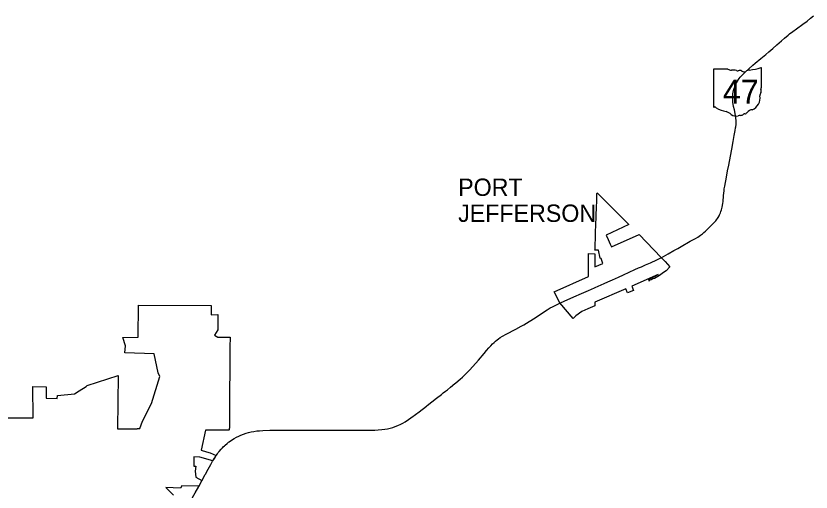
# Model space of a CAD drawing. Extents: x 0 to 34, y 0 to 22.
# Drawn here: x 5.5324 to 5.9007, y 18.3979 to 18.6182 of the extents above; entities that cross this region are included whole.
import ezdxf

# ---------------------------------------------------------------- set-up
doc = ezdxf.new("R2010")
doc.units = 0
for name, color, linetype in [('GM_X_Corporation', 7, 'Continuous'), ('GM_X_Corporation_Text', 7, 'Continuous'), ('GM_X_State_Location', 7, 'Continuous'), ('GM_X_State_Route', 7, 'Continuous'), ('GM_X_State_Shield', 7, 'Continuous')]:
    doc.layers.add(name, color=color, linetype=linetype)

msp = doc.modelspace()

# ---------------------------------------------------------------- linework, layer by layer
at = {"layer": 'GM_X_Corporation'}
msp.add_lwpolyline([(5.808174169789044, 18.511366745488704), (5.821044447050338, 18.517024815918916), (5.831236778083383, 18.506413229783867), (5.833056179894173, 18.50454531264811), (5.83531645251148, 18.50216216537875), (5.833549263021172, 18.500257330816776), (5.832319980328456, 18.49943728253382), (5.8310200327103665, 18.49852072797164), (5.830432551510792, 18.498096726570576), (5.829741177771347, 18.49766429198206), (5.828184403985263, 18.49679150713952), (5.82736013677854, 18.49652097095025), (5.8266708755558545, 18.49617554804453), (5.8258619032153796, 18.4959203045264), (5.825667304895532, 18.495515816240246), (5.825606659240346, 18.496414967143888), (5.828199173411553, 18.497675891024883), (5.829847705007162, 18.498591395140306), (5.817588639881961, 18.49312686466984), (5.8184746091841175, 18.491164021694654), (5.815717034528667, 18.490082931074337), (5.814906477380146, 18.491911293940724), (5.800549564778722, 18.485816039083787), (5.800520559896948, 18.484137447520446), (5.797253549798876, 18.482696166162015), (5.7945560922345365, 18.48140518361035), (5.791649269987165, 18.47942493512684), (5.790495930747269, 18.478195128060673), (5.784341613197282, 18.485399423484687), (5.781615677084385, 18.490484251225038), (5.797594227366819, 18.497718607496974), (5.79758579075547, 18.50824897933), (5.800564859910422, 18.508157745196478), (5.800546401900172, 18.50210468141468), (5.804286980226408, 18.503680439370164), (5.8034843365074, 18.505935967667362), (5.803039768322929, 18.506124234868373), (5.80217014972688, 18.50983264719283), (5.800589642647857, 18.50988538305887), (5.800654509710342, 18.51032625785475), (5.800682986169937, 18.512432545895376), (5.800763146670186, 18.51516744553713), (5.800831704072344, 18.51695467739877), (5.800899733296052, 18.518895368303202), (5.800971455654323, 18.52077910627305), (5.800999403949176, 18.521724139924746), (5.801027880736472, 18.522620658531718), (5.801081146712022, 18.524255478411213), (5.801144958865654, 18.52591930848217), (5.801186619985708, 18.526787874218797), (5.801269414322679, 18.52873595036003), (5.8013337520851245, 18.530422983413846), (5.801385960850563, 18.53184633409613), (5.801461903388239, 18.534006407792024), (5.801517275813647, 18.53595606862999), (5.801530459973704, 18.536375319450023), (5.816220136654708, 18.521714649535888), (5.805843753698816, 18.516747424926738), (5.8067154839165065, 18.5147023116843), (5.807585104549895, 18.512668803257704)], close=True, dxfattribs=at)
msp.add_lwpolyline([(5.525409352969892, 18.432222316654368), (5.540361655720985, 18.432277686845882), (5.540285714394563, 18.44669050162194), (5.546459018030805, 18.446609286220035), (5.546450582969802, 18.44519226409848), (5.546456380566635, 18.44131404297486), (5.551506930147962, 18.441193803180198), (5.551607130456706, 18.44264088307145), (5.559566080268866, 18.44336337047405), (5.561653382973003, 18.444678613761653), (5.56485710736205, 18.44669788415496), (5.565389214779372, 18.447169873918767), (5.579684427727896, 18.451787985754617), (5.579492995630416, 18.427136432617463), (5.588597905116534, 18.427111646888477), (5.588613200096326, 18.42738851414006), (5.589835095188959, 18.42738851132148), (5.591016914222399, 18.4306360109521), (5.595184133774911, 18.438813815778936), (5.599109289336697, 18.451374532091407), (5.598347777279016, 18.453032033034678), (5.596425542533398, 18.46189910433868), (5.582826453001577, 18.462407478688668), (5.5830679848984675, 18.465571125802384), (5.5818787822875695, 18.469464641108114), (5.58906145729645, 18.469504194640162), (5.589233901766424, 18.48436051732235), (5.622789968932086, 18.48419123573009), (5.622814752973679, 18.47998868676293), (5.625856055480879, 18.480037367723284), (5.6258510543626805, 18.472996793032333), (5.6244075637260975, 18.470464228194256), (5.625848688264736, 18.469606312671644), (5.627700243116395, 18.469601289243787), (5.6315752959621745, 18.469513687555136), (5.631513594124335, 18.46488450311), (5.631496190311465, 18.461457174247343), (5.631439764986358, 18.45771553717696), (5.631392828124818, 18.453867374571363), (5.631412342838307, 18.451968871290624), (5.631344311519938, 18.446645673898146), (5.6313116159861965, 18.436314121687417), (5.631312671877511, 18.434841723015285), (5.6313158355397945, 18.430883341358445), (5.631291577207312, 18.42824547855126), (5.631277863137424, 18.427930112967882), (5.631262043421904, 18.42755885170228), (5.631230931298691, 18.427226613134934), (5.631191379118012, 18.426949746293), (5.631143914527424, 18.426744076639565), (5.6310732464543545, 18.426483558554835), (5.620133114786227, 18.426476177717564), (5.618261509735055, 18.417322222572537), (5.62066944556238, 18.41645259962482), (5.622309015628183, 18.41612563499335), (5.625061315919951, 18.414806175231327), (5.62495900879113, 18.414663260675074), (5.624308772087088, 18.41365336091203), (5.62390955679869, 18.413002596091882), (5.623537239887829, 18.412355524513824), (5.617598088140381, 18.414120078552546), (5.6147413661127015, 18.41416859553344), (5.614822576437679, 18.409916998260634), (5.615779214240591, 18.409900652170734), (5.615344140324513, 18.407640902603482), (5.615712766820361, 18.404750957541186), (5.618474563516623, 18.40320367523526), (5.618475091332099, 18.403199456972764), (5.617073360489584, 18.400593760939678), (5.609287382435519, 18.400845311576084), (5.608588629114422, 18.399754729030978), (5.601788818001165, 18.400024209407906), (5.605381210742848, 18.396482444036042)], dxfattribs=at)
at = {"layer": 'GM_X_State_Route'}
for p, q in [((5.8307983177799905, 18.506133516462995), (5.831256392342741, 18.506367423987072)), ((5.618494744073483, 18.403153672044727), (5.620112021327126, 18.406043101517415)), ((5.617093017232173, 18.40054797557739), (5.618494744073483, 18.403153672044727))]:
    msp.add_line(p, q, dxfattribs=at)
for points in [[(5.860446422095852, 18.538075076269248), (5.860468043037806, 18.538236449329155), (5.860677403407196, 18.539487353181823), (5.861447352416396, 18.543582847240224), (5.862027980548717, 18.54658512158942), (5.8625252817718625, 18.549227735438), (5.863307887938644, 18.553317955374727), (5.863913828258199, 18.55652959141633), (5.86456512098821, 18.560056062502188), (5.865119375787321, 18.562903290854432), (5.865538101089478, 18.565184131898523), (5.865745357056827, 18.566431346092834), (5.865824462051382, 18.56692970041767), (5.865879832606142, 18.567348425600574), (5.865921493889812, 18.56772548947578), (5.865942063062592, 18.568129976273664), (5.865962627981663, 18.568590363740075), (5.865962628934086, 18.568995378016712), (5.865955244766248, 18.56955332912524), (5.865934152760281, 18.57004852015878), (5.865884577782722, 18.570836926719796), (5.86584239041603, 18.57126936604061), (5.865786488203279, 18.571729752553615), (5.8657094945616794, 18.572127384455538), (5.865144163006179, 18.574758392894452), (5.864795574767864, 18.576357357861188), (5.864591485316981, 18.577448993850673), (5.864480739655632, 18.578235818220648), (5.864404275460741, 18.579080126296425), (5.864370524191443, 18.57987433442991), (5.864381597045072, 18.580828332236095), (5.86442220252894, 18.581516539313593), (5.8645023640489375, 18.582201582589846), (5.864629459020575, 18.582933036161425), (5.864803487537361, 18.583709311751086), (5.865076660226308, 18.58467754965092), (5.865344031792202, 18.58548230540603), (5.8656166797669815, 18.586173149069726), (5.865903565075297, 18.586800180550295), (5.866173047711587, 18.587318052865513), (5.866594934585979, 18.58805266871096), (5.867051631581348, 18.588767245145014), (5.867419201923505, 18.58928669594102), (5.867908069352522, 18.589913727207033), (5.8684285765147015, 18.590514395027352), (5.869160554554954, 18.59127854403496), (5.8701483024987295, 18.592233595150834), (5.871812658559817, 18.593776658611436), (5.873702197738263, 18.595464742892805), (5.874786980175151, 18.596389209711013), (5.877362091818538, 18.598491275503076), (5.879693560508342, 18.60038819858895), (5.881152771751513, 18.601600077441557), (5.88302279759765, 18.603223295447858), (5.8848738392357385, 18.604868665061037), (5.886993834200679, 18.60676980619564), (5.888392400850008, 18.60797588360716), (5.8899929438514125, 18.609298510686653), (5.890723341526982, 18.609879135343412), (5.892187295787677, 18.611005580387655), (5.893967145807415, 18.612326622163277), (5.89683335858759, 18.614393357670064), (5.89883153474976, 18.615857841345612), (5.900454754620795, 18.617117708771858), (5.901859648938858, 18.618231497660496)], [(5.83896372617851, 18.510651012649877), (5.840524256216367, 18.511541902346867), (5.844750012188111, 18.5139266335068), (5.847136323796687, 18.515275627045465), (5.848217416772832, 18.515929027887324), (5.849437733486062, 18.516750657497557), (5.85036009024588, 18.5174488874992), (5.8510535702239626, 18.518013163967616), (5.851757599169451, 18.51864388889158), (5.852933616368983, 18.519776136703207), (5.854088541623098, 18.520934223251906), (5.854994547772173, 18.521819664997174), (5.85605718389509, 18.52291657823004), (5.856518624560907, 18.52341651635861), (5.856877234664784, 18.5238647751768), (5.85726589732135, 18.524423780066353), (5.857597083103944, 18.52495905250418), (5.858058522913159, 18.525783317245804), (5.858294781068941, 18.52625214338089), (5.858659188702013, 18.527066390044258), (5.858948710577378, 18.527798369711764), (5.859168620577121, 18.528443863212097), (5.859342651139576, 18.52904769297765), (5.859489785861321, 18.52965943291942), (5.859647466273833, 18.53048527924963), (5.859814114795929, 18.53152207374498), (5.859894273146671, 18.532252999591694), (5.860142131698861, 18.53519357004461), (5.860349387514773, 18.53734626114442), (5.860446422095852, 18.538075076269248)], [(5.831256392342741, 18.506367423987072), (5.834415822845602, 18.508095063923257), (5.837180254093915, 18.50963285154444), (5.83896372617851, 18.510651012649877)], [(5.784361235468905, 18.485353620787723), (5.786665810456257, 18.486380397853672), (5.789119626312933, 18.48747836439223), (5.790854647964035, 18.488242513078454), (5.794274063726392, 18.489750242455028), (5.795357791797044, 18.490221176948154), (5.7976549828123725, 18.491232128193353), (5.80030761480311, 18.492404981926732), (5.800732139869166, 18.492595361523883), (5.8035155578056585, 18.49384257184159), (5.80488564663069, 18.49444270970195), (5.806567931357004, 18.495200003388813), (5.8086694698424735, 18.496136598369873), (5.811480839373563, 18.497380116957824), (5.813803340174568, 18.49841849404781), (5.81637845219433, 18.4995829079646), (5.8190558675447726, 18.500823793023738), (5.820820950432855, 18.50161114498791), (5.822154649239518, 18.50219282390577), (5.823984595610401, 18.50302711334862), (5.82404946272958, 18.503058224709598), (5.826251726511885, 18.504004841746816), (5.829271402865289, 18.505353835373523), (5.8307983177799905, 18.506133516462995)], [(5.735987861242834, 18.44830445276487), (5.737227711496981, 18.449332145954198), (5.738181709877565, 18.450161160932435), (5.739233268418, 18.45111832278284), (5.7403011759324, 18.452135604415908), (5.741273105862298, 18.453101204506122), (5.742489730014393, 18.454343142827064), (5.7440596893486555, 18.456049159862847), (5.746595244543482, 18.458944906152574), (5.749207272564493, 18.461983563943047), (5.750353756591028, 18.46336209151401), (5.75144908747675, 18.46464885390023), (5.752331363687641, 18.465631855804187), (5.753100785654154, 18.466432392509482), (5.753862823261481, 18.46716700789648), (5.754536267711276, 18.467763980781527), (5.755317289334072, 18.468397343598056), (5.755952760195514, 18.46887249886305), (5.756736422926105, 18.469413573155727), (5.757760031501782, 18.470072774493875), (5.759386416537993, 18.47095135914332), (5.763962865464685, 18.473354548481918), (5.766383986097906, 18.474640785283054), (5.7675826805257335, 18.475304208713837), (5.768914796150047, 18.476054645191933), (5.7721496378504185, 18.47803225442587), (5.773823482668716, 18.479133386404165), (5.776807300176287, 18.481121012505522), (5.778391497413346, 18.482168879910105), (5.779864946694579, 18.483098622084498), (5.78087748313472, 18.483671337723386), (5.782768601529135, 18.484617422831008), (5.784361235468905, 18.485353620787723)], [(5.6309035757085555, 18.420920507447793), (5.6312004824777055, 18.421150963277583), (5.632284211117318, 18.421907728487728), (5.63348606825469, 18.422678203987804), (5.63454026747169, 18.42328678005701), (5.63557600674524, 18.42381941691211), (5.636542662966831, 18.42425132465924), (5.637726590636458, 18.424710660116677), (5.639029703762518, 18.42514942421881), (5.640147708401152, 18.425473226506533), (5.6413817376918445, 18.425770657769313), (5.642577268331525, 18.42599794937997), (5.6439389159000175, 18.4261888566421), (5.645148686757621, 18.42630592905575), (5.646783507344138, 18.426396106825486), (5.649947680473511, 18.426471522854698), (5.653586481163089, 18.42650368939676), (5.657223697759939, 18.426516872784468), (5.659386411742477, 18.426532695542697), (5.663076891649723, 18.42651950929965), (5.666979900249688, 18.42654271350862), (5.669394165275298, 18.426549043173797), (5.670670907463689, 18.42654218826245), (5.675892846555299, 18.42651476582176), (5.680059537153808, 18.426527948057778), (5.681747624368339, 18.426539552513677), (5.685967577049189, 18.42654060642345), (5.693300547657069, 18.426527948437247), (5.694828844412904, 18.42653269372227), (5.697654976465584, 18.42658543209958), (5.698572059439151, 18.426602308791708), (5.700203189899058, 18.426674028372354), (5.7018817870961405, 18.42681430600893), (5.703184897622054, 18.426985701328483), (5.704426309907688, 18.427214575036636), (5.705758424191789, 18.427524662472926), (5.706922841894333, 18.427850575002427), (5.708066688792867, 18.428241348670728), (5.709239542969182, 18.42870753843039), (5.710615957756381, 18.429329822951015), (5.711566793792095, 18.429812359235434), (5.712705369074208, 18.430469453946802), (5.714263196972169, 18.43145403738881), (5.716424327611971, 18.433019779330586), (5.7168762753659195, 18.433352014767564), (5.717469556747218, 18.433787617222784), (5.719184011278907, 18.435103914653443), (5.722503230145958, 18.437704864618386), (5.7228581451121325, 18.43799122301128), (5.727244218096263, 18.441397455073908), (5.7294470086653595, 18.443114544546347), (5.730276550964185, 18.443765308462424), (5.731318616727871, 18.4445727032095), (5.732238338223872, 18.445278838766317), (5.733642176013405, 18.446390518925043), (5.735726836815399, 18.448088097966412), (5.735987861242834, 18.44830445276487)], [(5.625080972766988, 18.41476038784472), (5.625690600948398, 18.41561207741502), (5.626121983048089, 18.41615631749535), (5.626496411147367, 18.416604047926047), (5.627494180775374, 18.41776529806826), (5.62800361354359, 18.41831058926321), (5.6284508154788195, 18.41879629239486), (5.628935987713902, 18.419281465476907), (5.629315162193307, 18.419612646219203), (5.630280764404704, 18.420437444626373), (5.6309035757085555, 18.420920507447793)], [(5.620112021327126, 18.406043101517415), (5.620194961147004, 18.406191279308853), (5.621465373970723, 18.40849057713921), (5.6226218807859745, 18.410630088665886), (5.623466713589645, 18.41215310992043), (5.623556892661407, 18.41230973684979)], [(5.623556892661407, 18.41230973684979), (5.623929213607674, 18.412956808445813), (5.6243284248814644, 18.41360757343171), (5.624978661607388, 18.414617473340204), (5.625080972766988, 18.41476038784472)], [(5.614172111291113, 18.39524730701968), (5.6142120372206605, 18.39532076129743), (5.615428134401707, 18.39753990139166), (5.617093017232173, 18.40054797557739)]]:
    msp.add_lwpolyline(points, dxfattribs=at)
at = {"layer": 'GM_X_State_Shield'}
for p, q in [((5.855407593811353, 18.593346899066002), (5.855407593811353, 18.576362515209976)), ((5.862181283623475, 18.593639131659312), (5.855627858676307, 18.593639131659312)), ((5.877785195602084, 18.585175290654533), (5.877785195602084, 18.594060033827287)), ((5.877783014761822, 18.585177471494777), (5.877785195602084, 18.585175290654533))]:
    msp.add_line(p, q, dxfattribs=at)
for centre, radius, start, end in [((5.855663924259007, 18.59338306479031), 0.0002592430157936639, 98.1301027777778, 188.13010277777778), ((5.863741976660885, 18.59561084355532), 0.0025145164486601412, 231.61950555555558, 271.11188333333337), ((5.864575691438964, 18.584103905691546), 0.009027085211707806, 80.48669166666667, 94.98826944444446), ((5.866625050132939, 18.593471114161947), 0.0007254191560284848, 219.79206111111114, 297.1023694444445), ((5.867689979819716, 18.59150804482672), 0.0015082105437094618, 54.466683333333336, 119.14113055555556), ((5.869636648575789, 18.594200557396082), 0.0018143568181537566, 233.85620555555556, 294.82819166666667), ((5.872840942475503, 18.58845158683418), 0.004774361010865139, 97.34618055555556, 120.7688527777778), ((5.869813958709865, 18.616794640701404), 0.02373123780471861, 275.8444694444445, 288.9064527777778), ((5.877536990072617, 18.594096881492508), 0.000249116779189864, 351.8620861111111, 97.738), ((5.877727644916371, 18.584523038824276), 0.00038552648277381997, 107.94398333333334, 210.33696666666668), ((5.877519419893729, 18.585140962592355), 0.0002666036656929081, 289.6038111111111, 7.734130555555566), ((5.871143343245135, 18.580326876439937), 0.005935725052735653, 292.3088861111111, 8.985838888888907), ((5.878677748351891, 18.581457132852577), 0.001683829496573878, 136.80649722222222, 186.92959444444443), ((5.875274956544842, 18.583399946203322), 0.002314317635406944, 340.0329638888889, 23.649566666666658), ((5.855666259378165, 18.576325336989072), 0.00026154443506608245, 171.9583861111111, 258.30661388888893), ((5.855705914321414, 18.578062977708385), 0.0019959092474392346, 267.33899444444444, 280.6038555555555), ((5.856114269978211, 18.575382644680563), 0.000719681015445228, 29.748380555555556, 93.27174722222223), ((5.865200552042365, 18.590642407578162), 0.017137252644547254, 240.41292222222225, 257.1985), ((5.860091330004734, 18.568732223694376), 0.0053619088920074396, 47.184155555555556, 75.83597222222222), ((5.873646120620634, 18.57159418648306), 0.0032508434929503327, 94.40312222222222, 142.57675), ((5.865890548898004, 18.575298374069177), 0.003402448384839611, 230.70037222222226, 286.29183611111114), ((5.867856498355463, 18.569426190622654), 0.0027957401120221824, 85.69512222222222, 111.20994722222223), ((5.868105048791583, 18.574026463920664), 0.0018128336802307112, 268.7770194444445, 315.54927222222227), ((5.869744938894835, 18.572381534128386), 0.0005103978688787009, 65.75173055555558, 132.64842222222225), ((5.869527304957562, 18.57471639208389), 0.0019176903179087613, 282.8731916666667, 323.27711111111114)]:
    msp.add_arc(centre, radius, start, end, dxfattribs=at)

# ---------------------------------------------------------------- texts
at = {"layer": 'GM_X_Corporation_Text'}
for s, p in [('PORT', (5.73721957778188, 18.53494407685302)), ('JEFFERSON', (5.73721957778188, 18.522921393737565))]:
    msp.add_text(s, height=0.008037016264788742, rotation=1.0000000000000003e-05, dxfattribs=at).set_placement(p)
at = {"layer": 'GM_X_State_Location'}
msp.add_text('47', height=1.6074032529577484e-05, rotation=1.0000000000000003e-05, dxfattribs=at).set_placement((5.862296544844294, 18.58255602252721))
for s, p in [('s', (5.866344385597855, 18.583725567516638)), ('r', (5.866343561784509, 18.583725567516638))]:
    msp.add_text(s, height=1.6074032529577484e-05, dxfattribs=at).set_placement(p)
at = {"layer": 'GM_X_State_Shield'}
msp.add_text('47', height=0.011189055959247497, dxfattribs=at).set_placement((5.859818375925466, 18.577560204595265))

doc.saveas('drawing.dxf')
